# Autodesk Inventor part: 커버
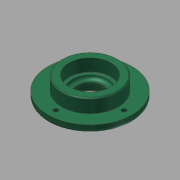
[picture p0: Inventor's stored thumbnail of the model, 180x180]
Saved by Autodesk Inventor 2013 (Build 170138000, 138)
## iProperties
Company: 한국ATC센터
Created: 2014-10
Part Number: 커버
Document SubType Name: Modeling
Designer: KYOUNG IL JANG
Density: 1 g/cm^3
Mass: 44.7286 g
Surface Area: 161.165 cm^2
Volume: 44.7286 cm^3
Material: 강철, 연강
Author: KYOUNG IL JANG
Revision Number: 1
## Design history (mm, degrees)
sketch "스케치1"
  geometry: C1 r 40 at (0, 0); 1 further point
  constraints: 1 centre point, 1 coincident
  dimensions: "d0" = 80 diameter of C1
extrude "돌출1" new body sketch "스케치1" distance "d1" = 7; taper "d2" = 0 deg
sketch "스케치2"
  geometry: C1 r 27 at (0, 0); 1 further point
  constraints: 1 centre point, 1 coincident
  dimensions: "d3" = 54 diameter of C1
extrude "돌출2" join sketch "스케치2" distance "d4" = 13; taper "d5" = 0 deg
sketch "스케치3"
  geometry: C1 r 20 at (0, 0); 1 further point
  constraints: 1 centre point, 1 coincident
  dimensions: "d6" = 40 diameter of C1
extrude "돌출3" join sketch "스케치3" distance "d7" = 5; taper "d8" = 0 deg
hole "구멍1" diameter "d11" = 25; stored, may be unused: countersink angle "d15" = 90 deg, drill point angle "d17" = 118 deg; dims "d9" = 10, "d10" = 10, "d12" = 6, "d13" = 32, "d14" = 8.3, "d16" = 8
hole "구멍2" diameter "d20" = 34; stored, may be unused: countersink angle "d24" = 90 deg, drill point angle "d26" = 0 deg; dims "d18" = 10, "d19" = 10, "d21" = 6, "d22" = 40, "d23" = 12, "d25" = 3
fillet "모깎기2" dims "d34" = 3
fillet "모깎기1" dims "d27" = 0.3
chamfer "모따기1" distance "d28" = 1; stored, may be unused: second distance "d29" = 2, angle "d30" = 45 deg
chamfer "모따기2" distance "d31" = 1.2; stored, may be unused: second distance "d32" = 2, angle "d33" = 30 deg
sketch "스케치4" dims "d35" = 65
  geometry: 3 further points
  constraints: 2 horizontal alignment, 1 coincident, 2 other
hole "구멍3" sketch "스케치4" at (32.5, 0) diameter "d36" = 4.5; stored, may be unused: countersink angle "d40" = 90 deg, drill point angle "d42" = 118 deg; dims "d37" = 6, "d38" = 8, "d39" = 4.4, "d41" = 13
node "솔리드1"
pattern_circular "원형 패턴1" dims angle "d44" = 360 deg
